Omron CX-Programmer project NuevoProyecto (CX-Programmer 9.50)

# PLC NewPLC1: CP1L-E EM

## Program P7_7_2 (cyclic task 0)
Local symbols
Ab 100.01 BOOL
As 100.00 BOOL
B 100.02 BOOL
C 100.03 BOOL
CNT_igual_3 15.00 BOOL
Etapa_0 10.00 BOOL
Etapa_1 10.01 BOOL
Etapa_2 10.02 BOOL
Etapa_3 10.03 BOOL
Etapa_4 10.04 BOOL
Etapa_5 10.05 BOOL
Etapa_6 10.06 BOOL
S 0.06 BOOL
a_0 0.01 BOOL
b_0 0.02 BOOL
b_1 0.03 BOOL
c_0 0.04 BOOL
c_1 0.05 BOOL
m 0.00 BOOL

### Section Sección1_Programa_principal
; Programa principal (Etapas 0 ... 6)

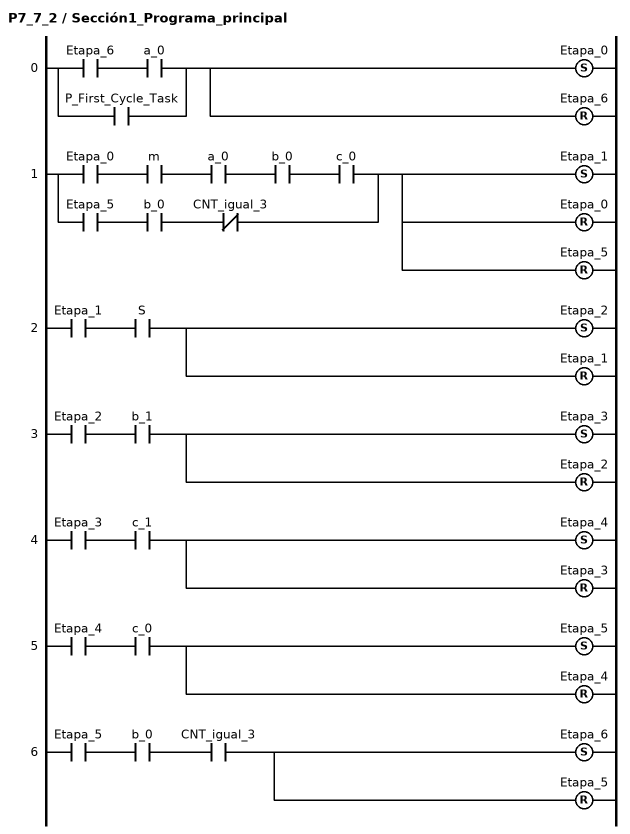
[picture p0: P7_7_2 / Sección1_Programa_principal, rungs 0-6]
; rung 0
LD Etapa_6
AND a_0
OR P_First_Cycle_Task
SET Etapa_0
RSET Etapa_6
; rung 1
LD Etapa_0
AND m
AND a_0
AND b_0
AND c_0
LD Etapa_5
AND b_0
ANDNOT CNT_igual_3
ORLD
SET Etapa_1
RSET Etapa_0
RSET Etapa_5
; rung 2
LD Etapa_1
AND S
SET Etapa_2
RSET Etapa_1
; rung 3
LD Etapa_2
AND b_1
SET Etapa_3
RSET Etapa_2
; rung 4
LD Etapa_3
AND c_1
SET Etapa_4
RSET Etapa_3
; rung 5
LD Etapa_4
AND c_0
SET Etapa_5
RSET Etapa_4
; rung 6
LD Etapa_5
AND b_0
AND CNT_igual_3
SET Etapa_6
RSET Etapa_5

### Section Sección2_Contador

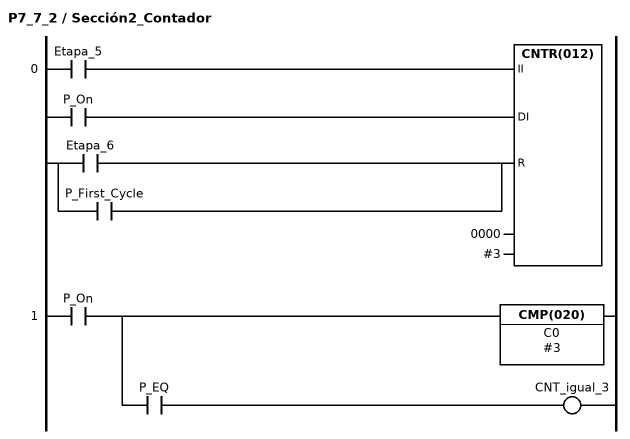
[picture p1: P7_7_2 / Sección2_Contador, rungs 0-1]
; rung 0
LD Etapa_5
LD P_On
LD Etapa_6
OR P_First_Cycle
CNTR(012) 0000 #3
; rung 1
LD P_On
CMP(020) C0 #3
AND P_EQ
OUT CNT_igual_3  // También se puede programar sin el KEEP del libro ya que al resetearse el contador también pasa a 0 la variable CNT_igual_3

### Section Sección3_Salidas

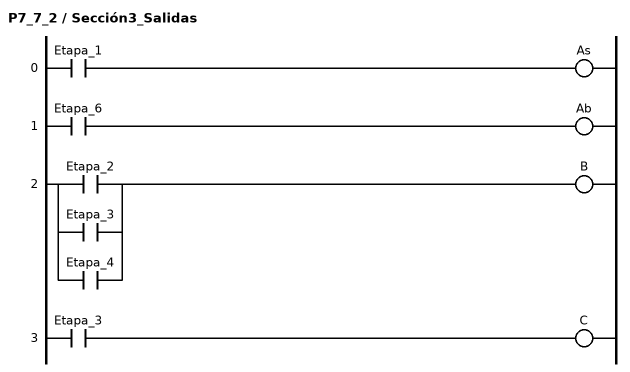
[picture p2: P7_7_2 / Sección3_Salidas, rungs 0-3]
; rung 0
LD Etapa_1
OUT As
; rung 1
LD Etapa_6
OUT Ab
; rung 2
LD Etapa_2
OR Etapa_3
OR Etapa_4
OUT B
; rung 3
LD Etapa_3
OUT C

### Section Sección4_END
; rung 0: Fin de programa
END(001)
